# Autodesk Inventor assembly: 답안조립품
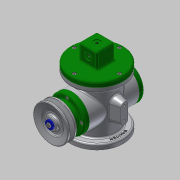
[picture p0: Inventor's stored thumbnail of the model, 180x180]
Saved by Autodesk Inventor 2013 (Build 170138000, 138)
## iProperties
Created: 2018-02
Part Number: 답안조립품
Document SubType Name: Assembly
Designer: Administrator
Author: Administrator
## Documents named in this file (18)
- C:\Users\Administrator\Desktop\480207V1018\답안조립품.iam
- C:\Users\Administrator\Desktop\480207V1018\E-링.ipt
- C:\Users\Administrator\Desktop\480207V1018\V-벨트풀리.ipt
- C:\Users\Administrator\Desktop\480207V1018\덮개.ipt
- C:\Users\Administrator\Desktop\480207V1018\뒤커버.ipt
- C:\Users\Administrator\Desktop\480207V1018\링크.ipt
- C:\Users\Administrator\Desktop\480207V1018\베어링 17 x 40 x 12.ipt
- C:\Users\Administrator\Desktop\480207V1018\볼트 M4 x 8.ipt
- C:\Users\Administrator\Desktop\480207V1018\볼트 M4 x 10.ipt
- C:\Users\Administrator\Desktop\480207V1018\슬라이더.ipt
- C:\Users\Administrator\Desktop\480207V1018\앞커버.ipt
- C:\Users\Administrator\Desktop\480207V1018\오일 실 17 30 8.ipt
- C:\Users\Administrator\Desktop\480207V1018\클레비스 핀 6 x 22.ipt
- 클레비스 핀 6 x 22.ipt
- C:\Users\Administrator\Desktop\480207V1018\와셔 4x16.ipt
- C:\Users\Administrator\Desktop\480207V1018\키 4 x 4 x 12.ipt
- C:\Users\Administrator\Desktop\480207V1018\편심축.ipt
- C:\Users\Administrator\Desktop\480207V1018\본체.ipt
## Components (2 placed, 2 different names)
1. E-링:1
2. V-벨트풀리:1
